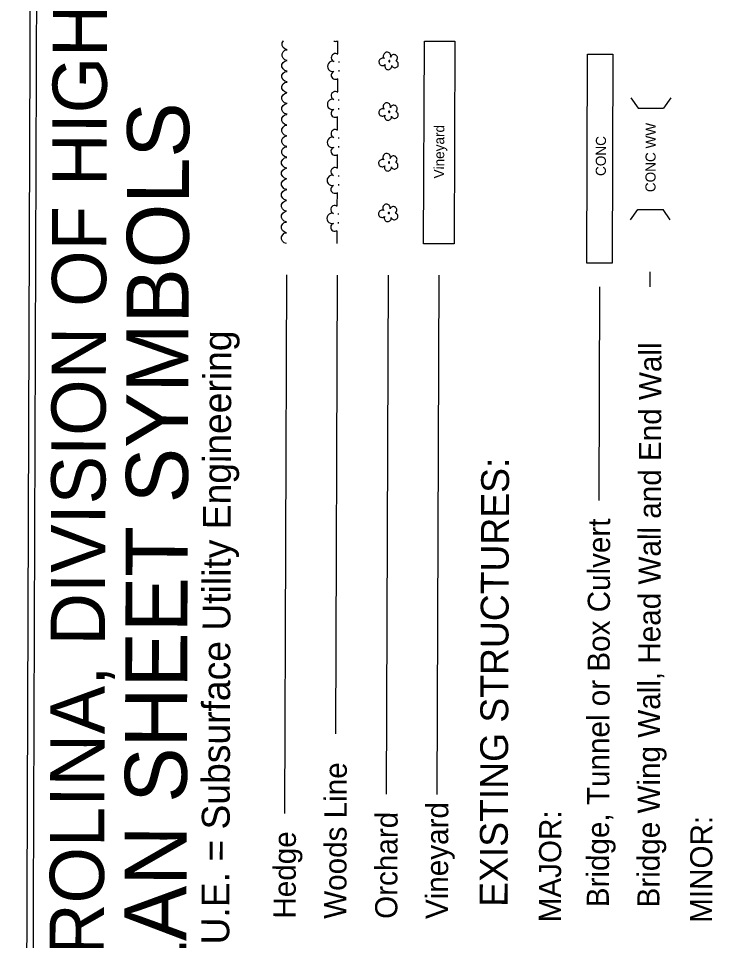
# Model space of a CAD drawing. Extents: x 2364794 to 2387902, y 795230 to 810426.
# Drawn here: x 2372651 to 2374589, y 805058 to 807607 of the extents above; entities that cross this region are included whole.
import ezdxf

# ---------------------------------------------------------------- set-up
doc = ezdxf.new("R2010")
doc.units = 0
doc.layers.add('Old_Level_22', color=7, linetype='Continuous')
doc.layers.add('Old_Level_63', color=7, linetype='Continuous')

msp = doc.modelspace()

# ---------------------------------------------------------------- linework, layer by layer
at = {"layer": 'Old_Level_22'}
msp.add_lwpolyline([(2380036.5, 798675.5), (2380077.7, 810340.9), (2372692.1, 810367), (2372650.9, 798701.5)], close=True, dxfattribs=at)
at = {"layer": 'Old_Level_63'}
for p, q in [((2373379.6, 807538.8), (2373383.2, 807544.4)), ((2373379.6, 807532.1), (2373379.6, 807538.8)), ((2373382.7, 807526.5), (2373379.6, 807532.1)), ((2373387.3, 807522.3), (2373382.7, 807526.5)), ((2373383.2, 807544.4), (2373383.5, 807544.7)), ((2373533.9, 807509.2), (2373534, 807544.2)), ((2373379.5, 807509), (2373383.1, 807514.6)), ((2373379.5, 807502.4), (2373379.5, 807509)), ((2373382.6, 807496.8), (2373379.5, 807502.4)), ((2373383.1, 807514.6), (2373387.6, 807518.4)), ((2373393.9, 807520.2), (2373387.3, 807522.3)), ((2373387.6, 807518.4), (2373393.6, 807519.8)), ((2373379.4, 807479.3), (2373382.9, 807484.9)), ((2373379.4, 807472.6), (2373379.4, 807479.3)), ((2373387.2, 807492.5), (2373382.6, 807496.8)), ((2373382.9, 807484.9), (2373387.5, 807488.7)), ((2373393.8, 807490.4), (2373387.2, 807492.5)), ((2373387.5, 807488.7), (2373393.5, 807490.1)), ((2373537.3, 807484.3), (2373537.3, 807487.8)), ((2373379.3, 807449.5), (2373382.8, 807455.1)), ((2373379.3, 807442.9), (2373379.3, 807449.5)), ((2373382.5, 807467), (2373379.4, 807472.6)), ((2373387.1, 807462.8), (2373382.5, 807467)), ((2373382.8, 807455.1), (2373387.4, 807458.9)), ((2373393.7, 807460.7), (2373387.1, 807462.8)), ((2373387.4, 807458.9), (2373393.4, 807460.3)), ((2373537.2, 807459.8), (2373537.2, 807463.3)), ((2373379.2, 807419.8), (2373382.7, 807425.4)), ((2373382.4, 807437.3), (2373379.3, 807442.9)), ((2373387, 807433), (2373382.4, 807437.3)), ((2373382.7, 807425.4), (2373387.3, 807429.2)), ((2373393.6, 807430.9), (2373387, 807433)), ((2373387.3, 807429.2), (2373393.3, 807430.6)), ((2373533.5, 807404.2), (2373533.6, 807439.2)), ((2373379.2, 807413.1), (2373379.2, 807419.8)), ((2373382.3, 807407.5), (2373379.2, 807413.1)), ((2373386.9, 807403.3), (2373382.3, 807407.5)), ((2373382.6, 807395.6), (2373387.2, 807399.4)), ((2373393.5, 807401.2), (2373386.9, 807403.3)), ((2373387.2, 807399.4), (2373393.2, 807400.8)), ((2373379.1, 807390), (2373382.6, 807395.6)), ((2373379.1, 807383.4), (2373379.1, 807390)), ((2373382.2, 807377.8), (2373379.1, 807383.4)), ((2373386.8, 807373.5), (2373382.2, 807377.8)), ((2373393.4, 807371.4), (2373386.8, 807373.5)), ((2373536.9, 807379.3), (2373536.9, 807382.8)), ((2374343.9, 807387.2), (2374363.9, 807358.5)), ((2374454, 807386.9), (2374433.9, 807358.2)), ((2373379, 807360.3), (2373382.5, 807365.9)), ((2373379, 807353.6), (2373379, 807360.3)), ((2373382.1, 807348), (2373379, 807353.6)), ((2373386.6, 807343.8), (2373382.1, 807348)), ((2373382.5, 807365.9), (2373387.1, 807369.7)), ((2373387.1, 807369.7), (2373393, 807371.1)), ((2373536.8, 807354.8), (2373536.9, 807358.3)), ((2374363.9, 807358.5), (2374433.9, 807358.2)), ((2373378.9, 807330.5), (2373382.4, 807336.1)), ((2373378.9, 807323.9), (2373378.9, 807330.5)), ((2373382, 807318.3), (2373378.9, 807323.9)), ((2373382.4, 807336.1), (2373387, 807339.9)), ((2373393.3, 807341.7), (2373386.6, 807343.8)), ((2373387, 807339.9), (2373392.9, 807341.3)), ((2373533.1, 807299.2), (2373533.3, 807334.2)), ((2373378.8, 807300.8), (2373382.3, 807306.4)), ((2373378.8, 807294.1), (2373378.8, 807300.8)), ((2373386.5, 807314), (2373382, 807318.3)), ((2373382.3, 807306.4), (2373386.9, 807310.2)), ((2373393.2, 807311.9), (2373386.5, 807314)), ((2373386.9, 807310.2), (2373392.8, 807311.6)), ((2373378.7, 807271), (2373382.2, 807276.6)), ((2373381.9, 807288.5), (2373378.8, 807294.1)), ((2373386.4, 807284.3), (2373381.9, 807288.5)), ((2373382.2, 807276.6), (2373386.8, 807280.4)), ((2373393.1, 807282.2), (2373386.4, 807284.3)), ((2373386.8, 807280.4), (2373392.7, 807281.8)), ((2373536.6, 807274.3), (2373536.6, 807277.8)), ((2373378.6, 807241.3), (2373382.1, 807246.9)), ((2373378.7, 807264.4), (2373378.7, 807271)), ((2373381.8, 807258.8), (2373378.7, 807264.4)), ((2373386.3, 807254.5), (2373381.8, 807258.8)), ((2373382.1, 807246.9), (2373386.7, 807250.7)), ((2373393, 807252.4), (2373386.3, 807254.5)), ((2373386.7, 807250.7), (2373392.6, 807252.1)), ((2373536.5, 807249.8), (2373536.5, 807253.3)), ((2373378.6, 807234.6), (2373378.6, 807241.3)), ((2373381.7, 807229), (2373378.6, 807234.6)), ((2373386.2, 807224.8), (2373381.7, 807229)), ((2373382, 807217.1), (2373386.6, 807220.9)), ((2373392.9, 807222.7), (2373386.2, 807224.8)), ((2373386.6, 807220.9), (2373392.5, 807222.3)), ((2373532.8, 807194.2), (2373532.9, 807229.2)), ((2373378.5, 807211.5), (2373382, 807217.1)), ((2373378.5, 807204.9), (2373378.5, 807211.5)), ((2373381.6, 807199.3), (2373378.5, 807204.9)), ((2373386.1, 807195), (2373381.6, 807199.3)), ((2373392.8, 807192.9), (2373386.1, 807195)), ((2373378.4, 807181.8), (2373381.9, 807187.4)), ((2373378.4, 807175.1), (2373378.4, 807181.8)), ((2373381.5, 807169.5), (2373378.4, 807175.1)), ((2373386, 807165.3), (2373381.5, 807169.5)), ((2373381.9, 807187.4), (2373386.5, 807191.2)), ((2373386.5, 807191.2), (2373392.4, 807192.6)), ((2373536.2, 807169.3), (2373536.2, 807172.8)), ((2373378.2, 807145.4), (2373378.3, 807152)), ((2373381.4, 807139.8), (2373378.2, 807145.4)), ((2373378.3, 807152), (2373381.8, 807157.6)), ((2373381.8, 807157.6), (2373386.4, 807161.4)), ((2373392.7, 807163.2), (2373386, 807165.3)), ((2373386.4, 807161.4), (2373392.3, 807162.8)), ((2373536.1, 807144.8), (2373536.1, 807148.3)), ((2373378.1, 807115.6), (2373378.2, 807122.3)), ((2373378.2, 807122.3), (2373381.7, 807127.9)), ((2373385.9, 807135.5), (2373381.4, 807139.8)), ((2373381.7, 807127.9), (2373386.3, 807131.7)), ((2373392.6, 807133.4), (2373385.9, 807135.5)), ((2373386.3, 807131.7), (2373392.2, 807133.1)), ((2373532.4, 807089.2), (2373532.5, 807124.2)), ((2373381.3, 807110), (2373378.1, 807115.6)), ((2373378.1, 807092.5), (2373381.6, 807098.1)), ((2373385.8, 807105.8), (2373381.3, 807110)), ((2373381.6, 807098.1), (2373386.1, 807101.9)), ((2373392.5, 807103.7), (2373385.8, 807105.8)), ((2373386.1, 807101.9), (2373392.1, 807103.3)), ((2373378, 807085.9), (2373378.1, 807092.5)), ((2373381.2, 807080.3), (2373378, 807085.9)), ((2373378, 807062.8), (2373381.5, 807068.4)), ((2373385.7, 807076), (2373381.2, 807080.3)), ((2373381.5, 807068.4), (2373386, 807072.2)), ((2373392.3, 807073.9), (2373385.7, 807076)), ((2373386, 807072.2), (2373392, 807073.6)), ((2373535.8, 807064.3), (2373535.8, 807067.8)), ((2374342.7, 807049.9), (2374362.9, 807078.5)), ((2374362.9, 807078.5), (2374432.9, 807078.2)), ((2374452.8, 807049.5), (2374432.9, 807078.2)), ((2373377.9, 807056.1), (2373378, 807062.8)), ((2373381.1, 807050.5), (2373377.9, 807056.1)), ((2373385.6, 807046.3), (2373381.1, 807050.5)), ((2373381.4, 807038.6), (2373385.9, 807042.4)), ((2373392.2, 807044.2), (2373385.6, 807046.3)), ((2373385.9, 807042.4), (2373391.9, 807043.8)), ((2373535.7, 807039.8), (2373535.7, 807043.3)), ((2373377.8, 807026.4), (2373377.9, 807033)), ((2373381, 807020.8), (2373377.8, 807026.4)), ((2373377.9, 807033), (2373381.4, 807038.6)), ((2373385.5, 807016.5), (2373381, 807020.8)), ((2373392.1, 807014.4), (2373385.5, 807016.5)), ((2373532, 806984.2), (2373532.2, 807019.2)), ((2373377.7, 807003.3), (2373381.3, 807008.9)), ((2373377.7, 806996.6), (2373377.7, 807003.3)), ((2373380.9, 806991), (2373377.7, 806996.6)), ((2373385.4, 806986.8), (2373380.9, 806991)), ((2373381.3, 807008.9), (2373385.8, 807012.7)), ((2373385.8, 807012.7), (2373391.8, 807014.1)), ((2373392, 806984.7), (2373385.4, 806986.8)), ((2373391.7, 806897.9), (2373386.5, 805409.1)), ((2373531.7, 806897.4), (2373527.2, 805629.6)), ((2373672.7, 806897.3), (2373667.6, 805462.7)), ((2373812.7, 806896.8), (2373807.6, 805462.2)), ((2374397.1, 806864.5), (2374397.3, 806906.4)), ((2374257.1, 806865), (2374255, 806274))]:
    msp.add_line(p, q, dxfattribs=at)
msp.add_lwpolyline([(2372709.6, 810279.4), (2372672.5, 799779.5), (2380015.4, 799753.5), (2380052.5, 810253.5)], close=True, dxfattribs=at)
for points in [[(2373771, 806983.7), (2373773, 807543.7), (2373857, 807543.4), (2373855, 806983.4), (2373771, 806983.7)], [(2373695.1, 807488.6), (2373697.5, 807492.8), (2373698.2, 807494.9), (2373698.6, 807497), (2373698.3, 807499.1), (2373697.6, 807500.9), (2373696.5, 807502.6), (2373695.1, 807504.4), (2373693.4, 807505.5), (2373691.6, 807506.2), (2373689.5, 807506.9), (2373687.4, 807506.5), (2373685.3, 807506.2), (2373683.2, 807504.8), (2373681.8, 807503.7), (2373680.8, 807502), (2373679.7, 807499.9), (2373680.1, 807502), (2373680.1, 807504.5), (2373679.4, 807506.2), (2373678.3, 807508.3), (2373677.3, 807510.1), (2373675.6, 807511.5), (2373673.5, 807512.5), (2373671.4, 807512.9), (2373669.3, 807513.2), (2373667.2, 807512.9), (2373665.1, 807512.2), (2373663.3, 807510.8), (2373661.5, 807509.1), (2373660.5, 807507.3), (2373659.8, 807505.2), (2373659.4, 807503.1), (2373659.4, 807501), (2373660.1, 807498.9), (2373661.2, 807497.2), (2373662.5, 807495.4)], [(2374222.3, 806930.2), (2374224.4, 807507.7), (2374294.4, 807507.5), (2374292.3, 806930), (2374222.3, 806930.2)], [(2373662.5, 807495.4), (2373660.4, 807496.5), (2373658.4, 807496.8), (2373656.2, 807496.5), (2373654.1, 807496.1), (2373652.4, 807495.1), (2373650.6, 807494.1), (2373649.2, 807492.3), (2373648.2, 807490.6), (2373647.5, 807488.1), (2373647.5, 807486.4), (2373647.8, 807484.3), (2373648.5, 807482.2), (2373649.5, 807480.4), (2373650.9, 807478.7), (2373653, 807477.6), (2373654.8, 807476.9), (2373656.9, 807476.5), (2373659, 807476.5), (2373661.1, 807476.9), (2373662.8, 807477.9), (2373664.9, 807479.3), (2373663.9, 807477.6), (2373663.5, 807475.5), (2373663.5, 807473.4), (2373664.2, 807471.6), (2373664.9, 807469.9), (2373666.3, 807468.1), (2373667.7, 807466.7), (2373669.4, 807465.6), (2373671.2, 807465.3), (2373673.6, 807464.9), (2373675.4, 807465.3), (2373677.1, 807466), (2373678.9, 807467.4), (2373680.3, 807468.4), (2373681.4, 807470.1), (2373682.4, 807472.2), (2373682.8, 807474), (2373682.8, 807476.1), (2373683.5, 807474.3), (2373684.9, 807472.6), (2373686.3, 807471.5), (2373688.4, 807470.8), (2373690.5, 807470.1), (2373692.2, 807470.1), (2373694.3, 807470.5), (2373696.1, 807471.5), (2373697.8, 807472.5), (2373699.2, 807473.9), (2373700.3, 807475.7), (2373701, 807477.4), (2373701, 807479.5), (2373701, 807481.6), (2373700.7, 807483.4), (2373699.3, 807485.1), (2373698.2, 807486.9), (2373695.1, 807488.6)], [(2373674.8, 807489.4), (2373674.8, 807488.4), (2373675.1, 807487.7), (2373675.5, 807487), (2373676.5, 807487), (2373677.2, 807487), (2373677.9, 807487.7), (2373677.9, 807488.7), (2373677.9, 807489.4), (2373677.2, 807490.1), (2373676.2, 807490.5), (2373675.5, 807490.1), (2373674.8, 807489.4)], [(2373694.6, 807348.6), (2373697, 807352.8), (2373697.7, 807354.9), (2373698.1, 807357), (2373697.8, 807359.1), (2373697.1, 807360.9), (2373696, 807362.6), (2373694.6, 807364.4), (2373692.9, 807365.5), (2373691.1, 807366.2), (2373689, 807366.9), (2373686.9, 807366.5), (2373684.8, 807366.2), (2373682.7, 807364.8), (2373681.3, 807363.7), (2373680.3, 807362), (2373679.2, 807359.9), (2373679.6, 807362), (2373679.6, 807364.5), (2373678.9, 807366.2), (2373677.8, 807368.3), (2373676.8, 807370.1), (2373675.1, 807371.5), (2373673, 807372.5), (2373670.9, 807372.9), (2373668.8, 807373.2), (2373666.7, 807372.9), (2373664.6, 807372.2), (2373662.8, 807370.8), (2373661, 807369.1), (2373660, 807367.3), (2373659.3, 807365.2), (2373658.9, 807363.1), (2373658.9, 807361), (2373659.6, 807358.9), (2373660.7, 807357.2), (2373662.1, 807355.4)], [(2373662.1, 807355.4), (2373660, 807356.5), (2373657.9, 807356.8), (2373655.8, 807356.5), (2373653.7, 807356.1), (2373651.9, 807355.1), (2373650.1, 807354.1), (2373648.7, 807352.3), (2373647.7, 807350.6), (2373647, 807348.1), (2373647, 807346.4), (2373647.3, 807344.3), (2373648, 807342.2), (2373649, 807340.4), (2373650.4, 807338.7), (2373652.5, 807337.6), (2373654.3, 807336.9), (2373656.4, 807336.5), (2373658.5, 807336.5), (2373660.6, 807336.9), (2373662.3, 807337.9), (2373664.4, 807339.3), (2373663.4, 807337.6), (2373663, 807335.5), (2373663, 807333.4), (2373663.7, 807331.6), (2373664.4, 807329.9), (2373665.8, 807328.1), (2373667.2, 807326.7), (2373668.9, 807325.6), (2373670.7, 807325.3), (2373673.1, 807324.9), (2373674.9, 807325.3), (2373676.6, 807326), (2373678.4, 807327.4), (2373679.8, 807328.4), (2373680.9, 807330.1), (2373681.9, 807332.2), (2373682.3, 807334), (2373682.3, 807336.1), (2373683, 807334.3), (2373684.4, 807332.6), (2373685.8, 807331.5), (2373687.9, 807330.8), (2373690, 807330.1), (2373691.7, 807330.1), (2373693.8, 807330.5), (2373695.6, 807331.5), (2373697.3, 807332.5), (2373698.7, 807333.9), (2373699.8, 807335.7), (2373700.5, 807337.4), (2373700.5, 807339.5), (2373700.5, 807341.6), (2373700.2, 807343.4), (2373698.8, 807345.1), (2373697.7, 807346.9), (2373694.6, 807348.6)], [(2373674.3, 807349.4), (2373674.3, 807348.4), (2373674.6, 807347.7), (2373675, 807347), (2373676, 807347), (2373676.7, 807347), (2373677.4, 807347.7), (2373677.4, 807348.7), (2373677.4, 807349.4), (2373676.7, 807350.1), (2373675.7, 807350.5), (2373675, 807350.1), (2373674.3, 807349.4)], [(2373694.1, 807208.7), (2373696.5, 807212.8), (2373697.3, 807214.9), (2373697.6, 807217), (2373697.3, 807219.1), (2373696.6, 807220.9), (2373695.5, 807222.6), (2373694.1, 807224.4), (2373692.4, 807225.5), (2373690.6, 807226.2), (2373688.5, 807226.9), (2373686.4, 807226.5), (2373684.3, 807226.2), (2373682.2, 807224.8), (2373680.8, 807223.7), (2373679.8, 807222), (2373678.7, 807219.9), (2373679.1, 807222), (2373679.1, 807224.5), (2373678.4, 807226.2), (2373677.4, 807228.3), (2373676.3, 807230.1), (2373674.6, 807231.5), (2373672.5, 807232.5), (2373670.4, 807232.9), (2373668.3, 807233.2), (2373666.2, 807232.9), (2373664.1, 807232.2), (2373662.3, 807230.8), (2373660.6, 807229.1), (2373659.5, 807227.3), (2373658.8, 807225.2), (2373658.4, 807223.1), (2373658.4, 807221), (2373659.1, 807218.9), (2373660.2, 807217.2), (2373661.6, 807215.4)], [(2373661.6, 807215.4), (2373659.5, 807216.5), (2373657.4, 807216.8), (2373655.3, 807216.5), (2373653.2, 807216.1), (2373651.4, 807215.1), (2373649.7, 807214.1), (2373648.2, 807212.3), (2373647.2, 807210.6), (2373646.5, 807208.1), (2373646.5, 807206.4), (2373646.8, 807204.3), (2373647.5, 807202.2), (2373648.6, 807200.4), (2373649.9, 807198.7), (2373652, 807197.6), (2373653.8, 807196.9), (2373655.9, 807196.5), (2373658, 807196.5), (2373660.1, 807196.9), (2373661.8, 807197.9), (2373663.9, 807199.3), (2373662.9, 807197.6), (2373662.5, 807195.5), (2373662.5, 807193.4), (2373663.2, 807191.6), (2373663.9, 807189.9), (2373665.3, 807188.1), (2373666.7, 807186.7), (2373668.5, 807185.6), (2373670.2, 807185.3), (2373672.6, 807184.9), (2373674.4, 807185.3), (2373676.2, 807186), (2373677.9, 807187.4), (2373679.3, 807188.4), (2373680.4, 807190.1), (2373681.4, 807192.2), (2373681.8, 807194), (2373681.8, 807196.1), (2373682.5, 807194.3), (2373683.9, 807192.6), (2373685.3, 807191.5), (2373687.4, 807190.8), (2373689.5, 807190.1), (2373691.2, 807190.1), (2373693.3, 807190.5), (2373695.1, 807191.5), (2373696.8, 807192.5), (2373698.2, 807193.9), (2373699.3, 807195.7), (2373700, 807197.4), (2373700, 807199.5), (2373700, 807201.6), (2373699.7, 807203.4), (2373698.3, 807205.1), (2373697.2, 807206.9), (2373694.1, 807208.7)], [(2373673.8, 807209.4), (2373673.8, 807208.4), (2373674.1, 807207.7), (2373674.5, 807207), (2373675.5, 807207), (2373676.2, 807207), (2373676.9, 807207.7), (2373676.9, 807208.7), (2373676.9, 807209.4), (2373676.2, 807210.1), (2373675.2, 807210.5), (2373674.5, 807210.1), (2373673.8, 807209.4)], [(2373693.6, 807068.7), (2373696.1, 807072.8), (2373696.8, 807074.9), (2373697.1, 807077), (2373696.8, 807079.1), (2373696.1, 807080.9), (2373695, 807082.6), (2373693.6, 807084.4), (2373691.9, 807085.5), (2373690.1, 807086.2), (2373688.1, 807086.9), (2373686, 807086.5), (2373683.8, 807086.2), (2373681.7, 807084.8), (2373680.3, 807083.7), (2373679.3, 807082), (2373678.2, 807079.9), (2373678.6, 807082), (2373678.6, 807084.5), (2373677.9, 807086.2), (2373676.9, 807088.3), (2373675.8, 807090.1), (2373674.1, 807091.5), (2373672, 807092.5), (2373669.9, 807092.9), (2373667.8, 807093.2), (2373665.7, 807092.9), (2373663.6, 807092.2), (2373661.8, 807090.8), (2373660.1, 807089.1), (2373659, 807087.3), (2373658.3, 807085.2), (2373657.9, 807083.1), (2373657.9, 807081), (2373658.6, 807078.9), (2373659.7, 807077.2), (2373661.1, 807075.4)], [(2373661.1, 807075.4), (2373659, 807076.5), (2373656.9, 807076.8), (2373654.8, 807076.5), (2373652.7, 807076.1), (2373650.9, 807075.1), (2373649.2, 807074.1), (2373647.8, 807072.3), (2373646.7, 807070.6), (2373646, 807068.1), (2373646, 807066.4), (2373646.3, 807064.3), (2373647, 807062.2), (2373648.1, 807060.4), (2373649.5, 807058.7), (2373651.5, 807057.6), (2373653.3, 807056.9), (2373655.4, 807056.5), (2373657.5, 807056.5), (2373659.6, 807056.9), (2373661.3, 807057.9), (2373663.5, 807059.3), (2373662.4, 807057.6), (2373662, 807055.5), (2373662, 807053.4), (2373662.7, 807051.6), (2373663.4, 807049.9), (2373664.8, 807048.1), (2373666.2, 807046.7), (2373668, 807045.6), (2373669.7, 807045.3), (2373672.2, 807044.9), (2373673.9, 807045.3), (2373675.7, 807046), (2373677.4, 807047.4), (2373678.8, 807048.4), (2373679.9, 807050.1), (2373680.9, 807052.2), (2373681.3, 807054), (2373681.3, 807056.1), (2373682, 807054.3), (2373683.4, 807052.6), (2373684.8, 807051.5), (2373686.9, 807050.8), (2373689, 807050.1), (2373690.7, 807050.1), (2373692.8, 807050.5), (2373694.6, 807051.5), (2373696.3, 807052.5), (2373697.7, 807053.9), (2373698.8, 807055.7), (2373699.5, 807057.4), (2373699.5, 807059.5), (2373699.5, 807061.6), (2373699.2, 807063.4), (2373697.8, 807065.1), (2373696.7, 807066.9), (2373693.6, 807068.7)], [(2373673.3, 807069.4), (2373673.3, 807068.4), (2373673.6, 807067.7), (2373674, 807067), (2373675, 807067), (2373675.7, 807067), (2373676.4, 807067.7), (2373676.4, 807068.7), (2373676.4, 807069.4), (2373675.7, 807070.1), (2373674.7, 807070.5), (2373674, 807070.1), (2373673.3, 807069.4)]]:
    msp.add_lwpolyline(points, dxfattribs=at)
for centre, radius, start, end in [((2373526.9, 807554.3), 11.1, 246.0486, 293.5466), ((2373526.7, 807498.3), 11.1, 50.5661, 251.3627), ((2373519.7, 807473.9), 14.4, 75.7614, 283.8339), ((2373526.6, 807449.3), 11.1, 108.2326, 309.0291), ((2373526.4, 807393.3), 11.1, 50.5661, 251.3627), ((2373519.3, 807368.9), 14.4, 75.7614, 283.8339), ((2373526.2, 807344.3), 11.1, 108.2326, 309.0291), ((2373526, 807288.3), 11.1, 50.5661, 251.3627), ((2373518.9, 807263.9), 14.4, 75.7614, 283.8339), ((2373525.8, 807239.3), 11.1, 108.2326, 309.0291), ((2373518.5, 807158.9), 14.4, 75.7614, 283.8339), ((2373525.6, 807183.3), 11.1, 50.5661, 251.3627), ((2373525.5, 807134.3), 11.1, 108.2326, 309.0291), ((2373518.2, 807053.9), 14.4, 75.7614, 283.8339), ((2373525.3, 807078.4), 11.1, 50.5661, 251.3627), ((2373525.1, 807029.4), 11.1, 108.2326, 309.0291)]:
    msp.add_arc(centre, radius, start, end, dxfattribs=at)

# ---------------------------------------------------------------- texts
for s, height, p in [('STATE OF NORTH CAROLINA, DIVISION OF HIGHWAYS', 149.933, (2372879.4, 802932.7)), ('CONVENTIONAL  PLAN SHEET SYMBOLS', 171.362, (2373107.1, 802841.2)), ('Vineyard', 28, (2373827.6, 807164.3)), ('CONC WW', 28, (2374412, 807126.4)), ('CONC', 28, (2374274.7, 807171.1)), ('*S.U.E. = Subsurface Utility Engineering', 77, (2373233.1, 804910)), ('Bridge Wing Wall, Head Wall and End Wall', 61.25, (2374422.9, 805149.7)), ('EXISTING STRUCTURES:', 77, (2374002.9, 805151.2)), ('Bridge, Tunnel or Box Culvert', 61.25, (2374282.9, 805150.2)), ('Woods Line', 61.25, (2373557.1, 805118.2)), ('Vineyard', 61.25, (2373838.1, 805117.5)), ('Orchard', 61.25, (2373698.1, 805118)), ('MAJOR:', 61.25, (2374150.6, 805108.5)), ('MINOR:', 61.25, (2374568.4, 805107)), ('Hedge', 61.25, (2373417.1, 805118.7))]:
    msp.add_text(s, height=height, rotation=89.7976, dxfattribs=at).set_placement(p)

doc.saveas('drawing.dxf')
